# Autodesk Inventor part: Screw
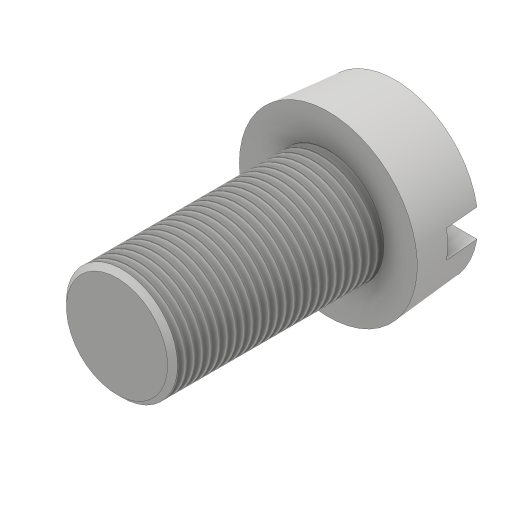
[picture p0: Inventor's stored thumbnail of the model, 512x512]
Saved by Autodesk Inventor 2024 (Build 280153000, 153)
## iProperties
Created: 2016-05
Part Number: Screw
Material: Generic
Document SubType Name: Modeling
Designer: CADCIM
Density: 1 g/cm^3
Appearance: Default
Author: CADCIM
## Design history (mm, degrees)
sketch "Sketch1"
  geometry: C1 r 16 at (0, 0); 1 further point
  constraints: 1 centre point, 1 coincident
  dimensions: "d0" = 32 diameter of C1
extrude "Extrusion1" new body sketch "Sketch1" distance "d1" = 12; taper "d2" = -5 deg
sketch "Sketch2"
  geometry: C1 r 10 at (0, 0); 1 further point
  constraints: 1 centre point, 1 coincident
  dimensions: "d4" = 20 diameter of C1
extrude "Extrusion2" join sketch "Sketch2" distance "d5" = 38; taper "d6" = 0 deg
workplane "Work Plane1"
thread "Thread1" dims "d10" = 10, "d11" = 0
chamfer "Chamfer1" distance "d12" = 0.9; stored, may be unused: second distance "d13" = 2, angle "d14" = 45 deg
sketch "Sketch4"
  geometry: L1 (-19.014, -2.5)-(20.179, -2.5); L2 (20.179, -2.5)-(20.179, 2.5); L3 (20.179, 2.5)-(-19.014, 2.5); L4 (-19.014, 2.5)-(-19.014, -2.5); L5 (0, 0)-(-19.039, 0)
  constraints: 10 end point, 2 horizontal, 2 parallel, 1 perpendicular, 1 other
  dimensions: "d15" = 5 distance of L3.end L1.start
extrude "Extrusion4" cut sketch "Sketch4" distance "d16" = 6; taper "d17" = 0 deg
body "Solid1"
